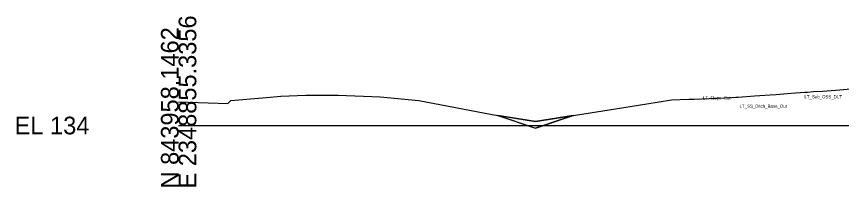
# Model space of a CAD drawing. Extents: x -26 to 2349090, y -10 to 844481.
# Drawn here: x 974.3 to 1105, y 16990.3 to 17017.3 of the extents above; entities that cross this region are included whole.
import ezdxf

# ---------------------------------------------------------------- set-up
doc = ezdxf.new("R2010")
doc.units = 0
for name, color, linetype in [('Exist Cross Section Cell', 7, 'Continuous'), ('Exist XS Ground Line', 7, 'Continuous'), ('Prop CMT Ditch DDE', 7, 'Continuous'), ('Prop Road Sect_ Recs - UUC (Outline)', 7, 'Continuous'), ('Scratch_Level_0', 7, 'Continuous')]:
    doc.layers.add(name, color=color, linetype=linetype)

msp = doc.modelspace()

# ---------------------------------------------------------------- linework, layer by layer
at = {"layer": 'Exist Cross Section Cell'}
msp.add_line((1000, 17000), (1150, 17000), dxfattribs=at)
at = {"layer": 'Exist XS Ground Line'}
msp.add_lwpolyline([(1000, 17003.74), (1004.69, 17003.6), (1007.81, 17003.47), (1008.25, 17003.97), (1013.91, 17004.43), (1016.21, 17004.65), (1020.14, 17004.82), (1025.26, 17004.81), (1031.94, 17004.55), (1038.09, 17003.95), (1049.7, 17001.74), (1056.58, 17000.63), (1068.24, 17002.5), (1074.19, 17003.45), (1078.12, 17004.06), (1080.84, 17004.19), (1081.7, 17004.21), (1087.69, 17004.45), (1088.32, 17004.48), (1088.67, 17004.51), (1091.28, 17004.73), (1093.72, 17004.88), (1094.68, 17004.94), (1096.42, 17005.08), (1097.77, 17005.19), (1099.24, 17005.29), (1099.66, 17005.32), (1100.56, 17005.38), (1102.01, 17005.48), (1103.43, 17005.58), (1104.76, 17005.67), (1106.5, 17005.8)], dxfattribs=at)
at = {"layer": 'Prop CMT Ditch DDE'}
for points in [[(1050.58, 17001.6), (1052.08, 17001.1), (1056.58, 16999.6)], [(1062.54, 17001.59), (1061.08, 17001.1), (1056.58, 16999.6)]]:
    msp.add_lwpolyline(points, dxfattribs=at)
at = {"layer": 'Prop Road Sect_ Recs - UUC (Outline)'}
msp.add_lwpolyline([(1050.58, 17001.6), (1056.58, 16999.6), (1062.54, 17001.59), (1056.58, 17000.63)], close=True, dxfattribs=at)

# ---------------------------------------------------------------- texts
at = {"layer": 'Exist Cross Section Cell'}
for s, p in [('E 2348855.3356', (1002.8, 16990)), ('N 843958.1462', (1000, 16990))]:
    msp.add_text(s, height=2.8, rotation=90, dxfattribs=at).set_placement(p)
msp.add_text('EL 134', height=2.8, dxfattribs=at).set_placement((974, 16998.6))
at = {"layer": 'Scratch_Level_0'}
for s, p in [('LT_Slope_Cut', (1083.06, 17004.12)), ('LT_Sub_OSS_DLT', (1099.17, 17004.32)), ('LT_SS_Ditch_Base_Out', (1088.88, 17002.83))]:
    msp.add_text(s, height=0.5, dxfattribs=at).set_placement(p)

doc.saveas('drawing.dxf')
